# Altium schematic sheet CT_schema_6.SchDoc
size 136 x 123 mm
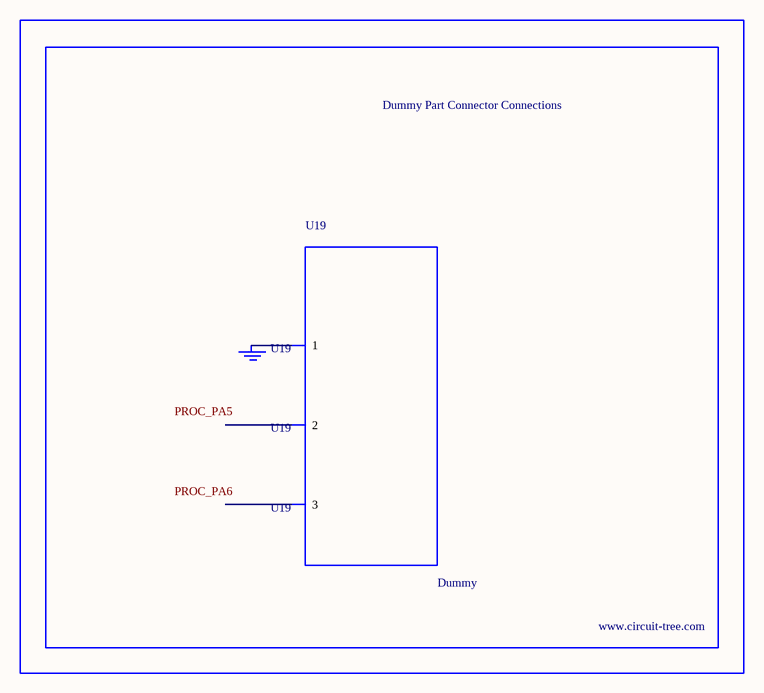
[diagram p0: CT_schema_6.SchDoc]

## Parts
BORDER5  (no value)
GND_INSTANCE_5_0  (no value)
U19  Dummy  [DUMMY_PACKAGE_184]

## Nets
NetGND_INSTANCE_5_0_0: GND_INSTANCE_5_0.0(GND) U19.1

Not connected (* = marked no-connect by the designer): U19 2 3

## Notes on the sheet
- Labels drawn without touching a wire or pin: PROC_PA5, PROC_PA6

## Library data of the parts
BORDER5 = BORDER_PAGE5
GND_INSTANCE_5_0 = GND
